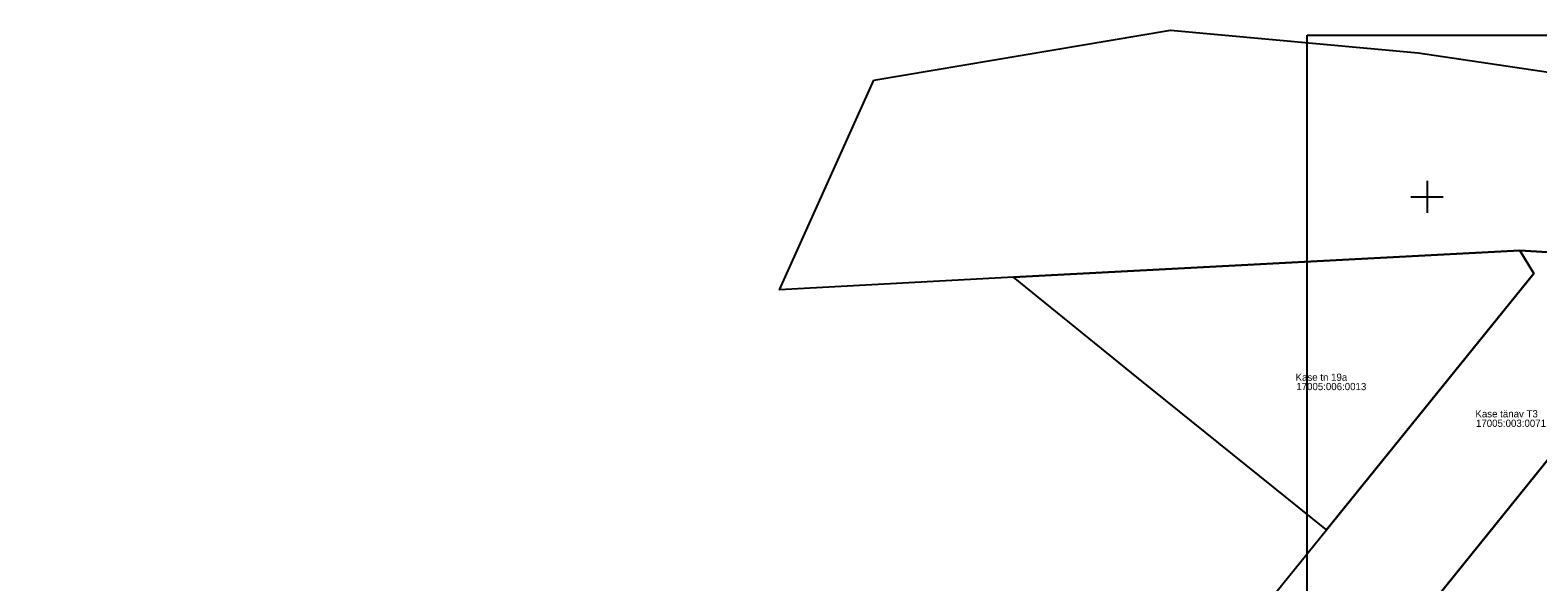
# Model space of a CAD drawing. Extents: x 640876 to 641418, y 6455595 to 6456085.
# Drawn here: x 640876.4 to 641063.8, y 6455952.1 to 6456020.7 of the extents above; entities that cross this region are included whole.
import ezdxf

# ---------------------------------------------------------------- set-up
doc = ezdxf.new("R2010")
doc.units = 0
for name, color, linetype in [('PIIR', 7, 'Continuous'), ('VORK', 7, 'Continuous'), ('VORMISTUS', 7, 'Continuous')]:
    doc.layers.add(name, color=color, linetype=linetype)

msp = doc.modelspace()

# ---------------------------------------------------------------- linework, layer by layer
at = {"layer": 'PIIR'}
for points in [[(640981.25, 6456014.49), (641018.11, 6456020.73), (641048.89, 6456017.91), (641071.8, 6456014.51), (641086.43, 6456012.78), (641194.48, 6456014.88), (641224.33, 6456016.64), (641234.96, 6456017.83), (641241.97, 6456004.88), (641237.36, 6455995.24), (641222.58, 6455998.61), (641084.84, 6455991.92), (641061.51, 6455993.34), (640998.61, 6455989.99), (640969.54, 6455988.44)], [(641014.16, 6455977.42), (640998.61, 6455989.99), (641061.51, 6455993.34), (641063.25, 6455990.48), (641037.5, 6455958.58)], [(641074.95, 6455979.64), (641102.26, 6455951.82), (641075.14, 6455914.24), (641043, 6455940)]]:
    msp.add_lwpolyline(points, close=True, dxfattribs=at)
for points in [[(640876.41, 6455757.97), (640962.33, 6455865.02), (640971.01, 6455875.38), (640993.57, 6455904.12), (641012.36, 6455927.46), (641024.93, 6455943.02), (641037.5, 6455958.58), (641063.25, 6455990.48), (641061.51, 6455993.34), (641084.84, 6455991.92)], [(641074.95, 6455979.64), (641043, 6455940), (641027.94, 6455921.32), (641010.57, 6455899.76), (641030.33, 6455884.46), (641051.68, 6455867.61), (641061.31, 6455859.9), (641055.55, 6455852.8), (641049.71, 6455856.81), (641032.25, 6455870.2), (641005.01, 6455891.09), (640984.64, 6455865.92), (640977.72, 6455857.07), (640952.64, 6455826.1), (640933.13, 6455802.02)]]:
    msp.add_lwpolyline(points, dxfattribs=at)
at = {"layer": 'VORK'}
for p, q in [((641050, 6456002), (641050, 6455998)), ((641048, 6456000), (641052, 6456000))]:
    msp.add_line(p, q, dxfattribs=at)
at = {"layer": 'VORMISTUS'}
for p, q in [((641035.12, 6455709.6), (641035.12, 6456020.09)), ((641035.12, 6456020.09), (641256.3, 6456020.09))]:
    msp.add_line(p, q, dxfattribs=at)

# ---------------------------------------------------------------- texts
at = {"layer": 'PIIR'}
for s, p in [('Kase tn 19a', (641033.66, 6455977.12)), ('17005:006:0013', (641033.75, 6455975.96))]:
    msp.add_text(s, height=0.9, dxfattribs=at).set_placement(p)
for s, p in [('Kase tänav T3', (641056.01, 6455972.57)), ('17005:003:0071', (641056.08, 6455971.39))]:
    msp.add_text(s, height=0.9, rotation=360, dxfattribs=at).set_placement(p)

doc.saveas('drawing.dxf')
